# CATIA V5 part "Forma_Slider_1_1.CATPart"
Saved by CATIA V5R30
Part number: Forma_Slider_1_1
Publications: "DrillHole_CapScrew_E1200_1.5_E 3060_12_23_1.1.1.1", "DrillHole_CapScrew_E1200_1.6_E 3060_12_23_1.1.1.1", "DrillHole_CapScrew_E1200_1.7_E 3060_12_23_1.1.1.1", "DrillHole_CapScrew_E1200_1.8_E 3060_12_23_1.1.1.1"
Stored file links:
  E:\Bakalarka\Model\Forma_v7\Forma_Slider_1_1.CATPart
  E:\Bakalarka\Model\Forma_v7\Forma.CATProduct
  E:\Bakalarka\Model\Forma_v7\TlgItf_Slider_1.CATProduct

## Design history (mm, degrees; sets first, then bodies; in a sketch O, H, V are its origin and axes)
Body1 (main body)
Body2 "DrillHole"
  Solid1: linked copy from another document
Body3 "DrillHole"
  Solid2: linked copy from another document
Body4 "DrillHole"
  Solid3: linked copy from another document
Body5 "DrillHole"
  Solid4: linked copy from another document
